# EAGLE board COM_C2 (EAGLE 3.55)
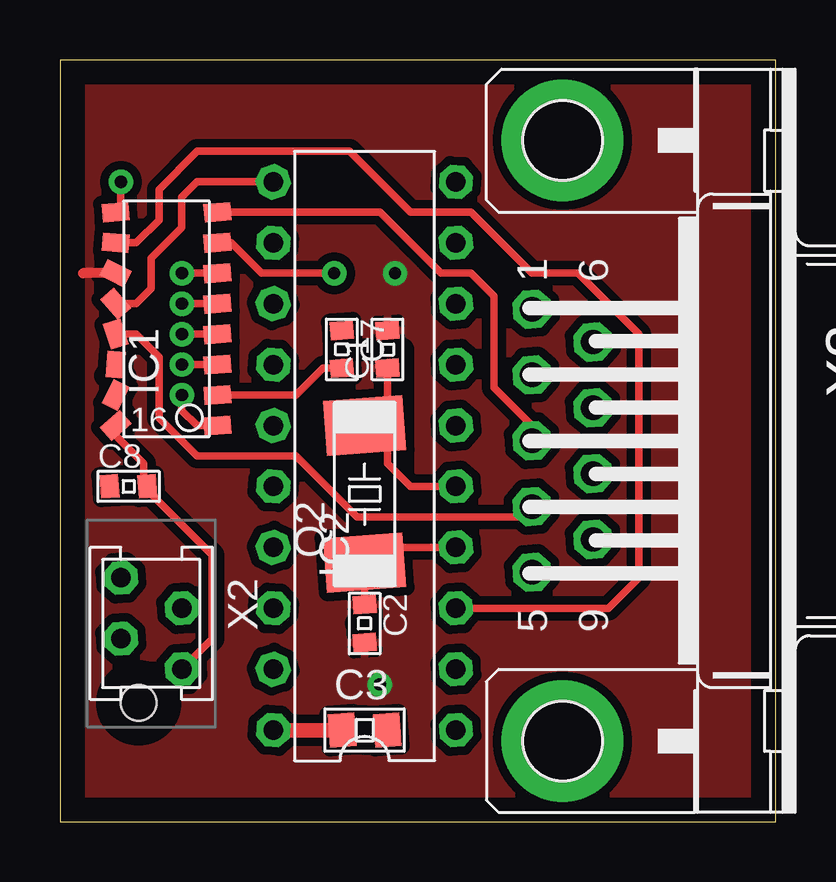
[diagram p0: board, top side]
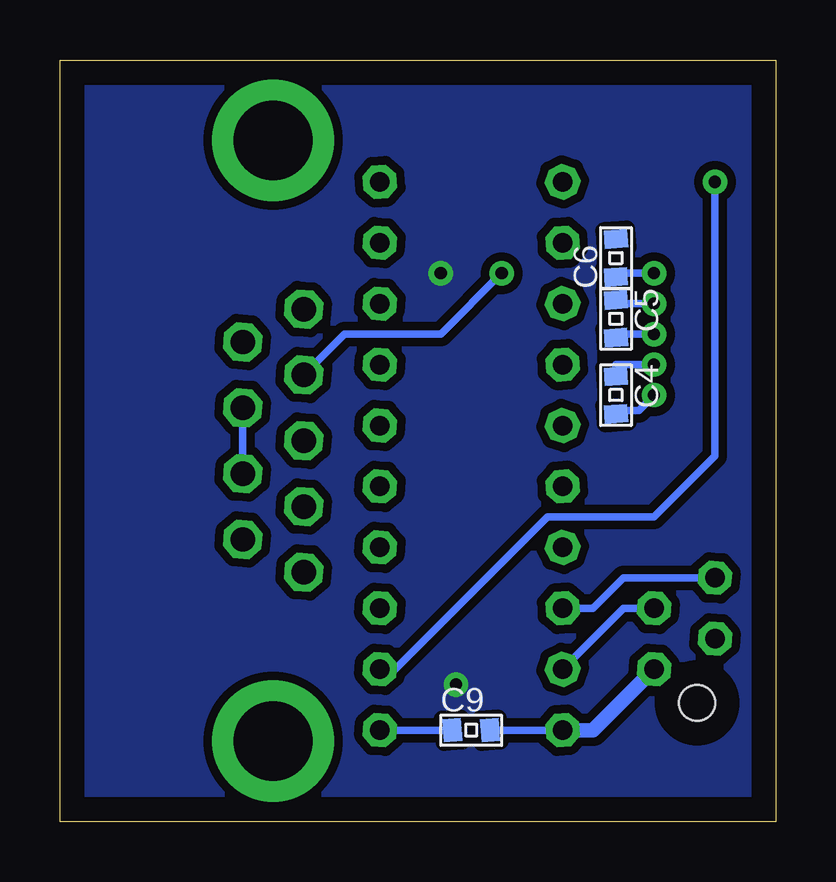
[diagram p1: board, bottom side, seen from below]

Size 29.84 x 31.75 mm. Coordinates in mm from the lower left corner, seen from the top.
Outline: 0,0 29.84,0 29.84,31.75 0,31.75 0,0
Copper layers used: Top, Bottom
tRestrict: 11 lines
bRestrict: 2 lines

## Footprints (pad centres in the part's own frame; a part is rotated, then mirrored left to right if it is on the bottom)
03 = smd 0.762 x 0.965 rotated 4.4:  0.787,0 | smd 0.762 x 0.965 rotated 4.3:  -0.787,0
05 = smd 1.092 x 1.397 rotated 4.4:  0.94,0 | smd 1.092 x 1.397 rotated 4.3:  -0.94,0
-16SS = smd 0.762 x 1.118 rotated 4.3:  -4.445,-2.121;  3.175,2.121 | smd 0.762 x 1.118 rotated 139.3:  -4.445,2.121 | smd 0.762 x 1.118 rotated 4.4:  -3.175,-2.121 | smd 0.762 x 1.118 rotated 4.5:  -1.905,-2.121 | smd 0.762 x 1.118 rotated 116.8:  -3.175,2.121 | smd 0.762 x 1.118 rotated 94.3:  -1.905,2.121 | smd 0.762 x 1.118 rotated 4.6:  -0.635,-2.121 | smd 0.762 x 1.118 rotated 71.8:  -0.635,2.121 | smd 0.762 x 1.118 rotated 4.7:  0.635,-2.121;  1.905,-2.121 | smd 0.762 x 1.118 rotated 49.3:  0.635,2.121 | smd 0.762 x 1.118 rotated 4.8:  3.175,-2.121 | smd 0.762 x 1.118 rotated 26.8:  1.905,2.121 | smd 0.762 x 1.118 rotated 4.9:  4.445,-2.121 | smd 0.762 x 1.118 rotated 5:  4.445,2.121
L-20 = drill 0.813 pad 1.397 octagon:  -11.43,-3.81;  -8.89,-3.81;  3.81,-3.81;  6.35,-3.81;  -6.35,-3.81;  -3.81,-3.81;  1.27,-3.81;  -1.27,-3.81;  8.89,-3.81;  11.43,-3.81;  11.43,3.81;  8.89,3.81;  6.35,3.81;  3.81,3.81;  1.27,3.81;  -1.27,3.81;  -3.81,3.81;  -6.35,3.81;  -8.89,3.81;  -11.43,3.81
T41 = smd 2.286 x 3.302 rotated 4.3:  -2.857,0 | smd 2.286 x 3.302 rotated 4.4:  2.857,0
04 = drill 0.813 pad 1.397 octagon:  0,0;  1.27,2.54;  2.54,0;  3.81,2.54 | hole 1.5: -1.4,1.8
9HP = drill 1.016 pad 1.6 octagon:  -5.486,-1.27;  -2.743,-1.27;  0,-1.27;  2.743,-1.27;  5.486,-1.27;  -4.115,1.27;  -1.372,1.27;  1.372,1.27;  4.115,1.27 | drill 3.302 pad 5.08 round:  -12.522,0;  12.522,0

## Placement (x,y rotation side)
C1  C_0603  [03]  13.65,19.68 90 top
C2  C_0603  [03]  12.7,8.26 270 top
C3  C_0603  [05]  12.7,3.81 0 top
C4  C_0603  [03]  6.67,17.78 270 bottom
C5  C_0603  [03]  6.67,20.95 270 bottom
C6  C_0603  [03]  6.67,23.5 90 bottom
C7  C_0603  [03]  11.75,19.68 270 top
C8  C_0603  [03]  2.86,13.97 0 top
C9  C_0603  [03]  12.7,3.81 0 bottom
IC1  MAX202CPE  [-16SS]  4.45,20.95 90 top
IC2  89C2051P  [L-20]  12.7,15.24 90 top
Q2  MM40SMD  [T41]  12.7,13.65 90 top
X2  FL04S  [04]  5.08,6.35 90 top
X3  F09HP  [9HP]  20.95,15.88 270 top

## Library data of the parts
C1-C9 = SMD_C
IC1 = MAXIM
IC2 = ATMEL
Q2 = QUARTZ
X2 = CON-ML
X3 = SUBD-US

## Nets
5P: C3. C8. C9. IC1. IC2. X2.
C2C: IC2. X2.
C2D: IC2. X2.
CV+: C7. IC1.
CV-: C6. IC1.
GND: C1. C2. C3. C6. C7. C8. IC1. IC2. X2. X3.
MC_RX: IC1. IC2.
MC_TX: IC1. IC2.
N$1: C2. IC2. Q2.
N$2: C1. IC2. Q2.
N$4: C4. IC1.
N$7: C9. IC2.
N$11: IC1. X3.
N$12: IC1. IC2.
N$15: X3.
N$20: C4. IC1.
N$22: C5. IC1.
N$23: C5. IC1.
PC_RX: IC1. X3.
PC_TX: IC1. X3.

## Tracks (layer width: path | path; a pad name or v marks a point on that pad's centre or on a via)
5P
  Top 0.305: 3.49,13.97 3.49,14.92 2.32,16.09 2.32,16.51 | 3.49,13.97 6.35,11.11 6.35,7.62 5.08,6.35 | 3.49,13.97 3.65,13.97
  Top 0.61: IC2. C3.
  Bottom 0.305: IC2. 11.91,3.81
  Bottom 0.61: 5.08,6.35 7.62,3.81 IC2.
C2C
  Bottom 0.305: X2. 6.35,10.16 7.62,8.89 8.89,8.89
C2D
  Bottom 0.305: 5.08,8.89 6.35,8.89 8.89,6.35
CV+
  Top 0.305: 6.57,17.78 9.84,17.78 10.96,18.9 11.75,18.9
CV-  (via drill 0.51 pad 1.02)
  Top 0.305: v5.08,22.86 6.57,22.86
  Bottom 0.305: v5.08,22.86 6.67,22.86 C6.
GND  (via drill 0.51 pad 1.02)
  Top 0.406: 2.32,22.86 0.95,22.86
  Bottom 0.305: 6.67,24.28 6.67,24.13
  other vias: 13.97,22.86 13.34,5.71
  pour Bottom (isolate 0.356): 0.64,31.11 29.21,31.11 29.21,0.64 0.64,0.64
  pour Top (isolate 0.356): 0.64,31.11 29.21,31.11 29.21,0.64 0.64,0.64
MC_RX  (via drill 0.51 pad 1.02)
  Top 0.305: v2.54,26.67 2.54,25.4 IC1.
  Bottom 0.305: v2.54,26.67 2.54,15.24 5.08,12.7 9.53,12.7 15.88,6.35 16.51,6.35
MC_TX
  Top 0.305: 16.51,8.89 22.86,8.89 24.13,10.16 24.13,20.32 21.59,22.86 19.68,22.86 17.14,25.4 14.61,25.4 12.06,27.94 5.71,27.94 4.13,26.35 4.13,25.08 3.17,24.13 2.32,24.13
N$1
  Top 0.305: C2. 12.7,10.79 | 12.7,10.79 12.7,11.43 16.51,11.43 | 12.7,10.79 12.7,9.84
N$2
  Top 0.305: 16.51,13.97 14.61,13.97 13.65,14.92 13.65,16.51 | 13.65,16.51 C1. | 13.65,16.51 Q2.
N$4  (via drill 0.51 pad 1.02)
  Top 0.305: v5.08,19.05 6.57,19.05
  Bottom 0.305: v5.08,19.05 6.67,19.05 C4.
N$7
  Bottom 0.305: C9. 16.51,3.81
N$11
  Top 0.305: 2.32,20.32 3.17,20.32 4.13,19.37 4.13,16.83 5.71,15.24 9.84,15.24 12.38,12.7 19.25,12.7 19.68,13.13
N$12
  Top 0.305: 2.32,21.59 3.17,21.59 3.81,22.23 3.81,23.5 5.08,24.77 5.08,26.04 5.71,26.67 8.89,26.67
N$15
  Bottom 0.305: 22.23,14.5 22.23,17.25
N$20  (via drill 0.51 pad 1.02)
  Top 0.305: v5.08,17.78 5.08,17.14 5.71,16.51 6.57,16.51
  Bottom 0.305: v5.08,17.78 5.71,17.14 6.67,17.14 6.67,16.99
N$22  (via drill 0.51 pad 1.02)
  Top 0.305: v5.08,21.59 6.57,21.59
  Bottom 0.305: v5.08,21.59 6.67,21.59 C5.
N$23  (via drill 0.51 pad 1.02)
  Top 0.305: v5.08,20.32 6.57,20.32
  Bottom 0.305: v5.08,20.32 6.67,20.32 6.67,20.17
PC_RX
  Top 0.305: 6.57,25.4 13.34,25.4 15.88,22.86 17.14,22.86 18.1,21.91 18.1,18.1 19.68,16.51 19.68,15.88
PC_TX  (via drill 0.51 pad 1.02)
  Top 0.305: v11.43,22.86 8.41,22.86 7.14,24.13 6.57,24.13
  Bottom 0.305: 19.68,18.62 17.98,20.32 13.97,20.32 v11.43,22.86

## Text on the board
bStop: PLI12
